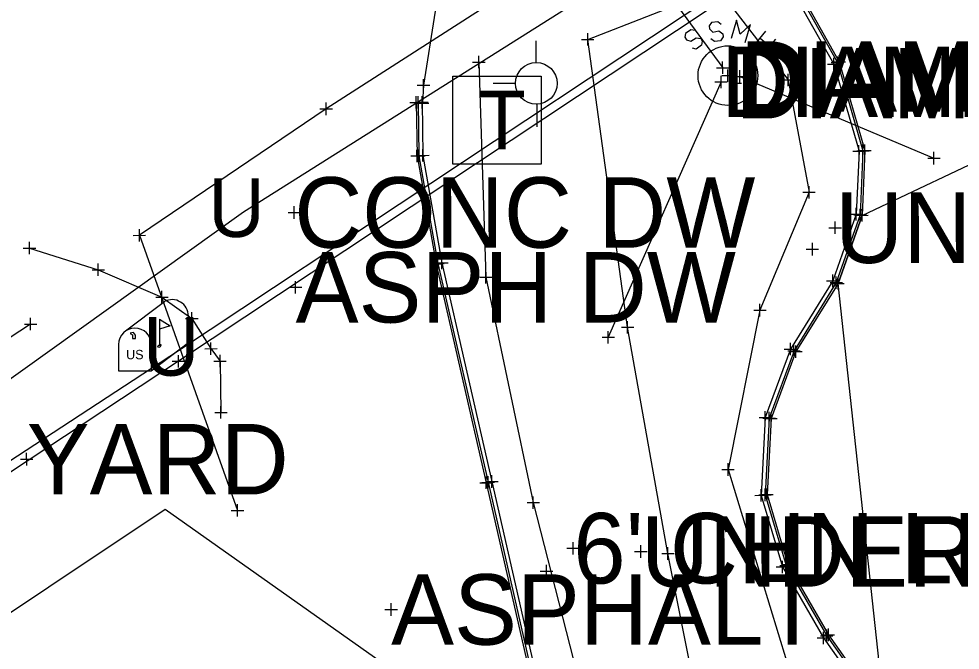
# Model space of a CAD drawing. Extents: x -1 to 1157254, y -1 to 2021979.
# Drawn here: x 1150680.9 to 1150776.9, y 2019832.5 to 2019897 of the extents above; entities that cross this region are included whole.
import ezdxf

# ---------------------------------------------------------------- set-up
doc = ezdxf.new("R2010")
doc.units = 0
for name, color, linetype in [('S_BUILDING_ANNOT', 7, 'Continuous'), ('S_CAL_CORNER_ANNOT', 7, 'Continuous'), ('S_CATCH_BASIN', 7, 'Continuous'), ('S_CATCH_BASIN_ANNOT', 7, 'Continuous'), ('S_CONTOUR_MAJOR', 7, 'Continuous'), ('S_CONTOUR_MINOR', 7, 'Continuous'), ('S_CROSS_DRAIN', 7, 'Continuous'), ('S_CTL_TABLE', 7, 'Continuous'), ('S_DROP_INLET', 7, 'Continuous'), ('S_EDGE_BITUMINOUS_ANNOT', 7, 'Continuous'), ('S_EDGE_PAVEMENT', 7, 'Continuous'), ('S_EDGE_PAVEMENT_ANNOT', 7, 'Continuous'), ('S_ENV_CONSTRAINT', 7, 'Continuous'), ('S_FENCE', 7, 'Continuous'), ('S_GAS_PUMP_ISLAND_ANNOT', 7, 'Continuous'), ('S_GATE', 7, 'Continuous')]:
    doc.layers.add(name, color=color, linetype=linetype)

msp = doc.modelspace()

# ---------------------------------------------------------------- linework, layer by layer
at = {"layer": 'S_BUILDING_ANNOT'}
for p, q in [((1150764.407, 2019891.922), (1150764.404, 2019893.194)), ((1150764.593, 2019891.999), (1150764.59, 2019893.271)), ((1150752.694, 2019891.403), (1150752.691, 2019892.675)), ((1150752.694, 2019891.403), (1150752.691, 2019892.675)), ((1150763.398, 2019892.401), (1150764.671, 2019892.403)), ((1150763.769, 2019892.557), (1150765.042, 2019892.559)), ((1150763.955, 2019892.634), (1150765.228, 2019892.636)), ((1150764.036, 2019891.766), (1150764.033, 2019893.038)), ((1150764.035, 2019892.402), (1150764.035, 2019892.402)), ((1150764.406, 2019892.558), (1150764.406, 2019892.558)), ((1150764.592, 2019892.635), (1150764.592, 2019892.635)), ((1150752.056, 2019892.038), (1150753.328, 2019892.04)), ((1150752.056, 2019892.038), (1150753.328, 2019892.04)), ((1150752.525, 2019889.952), (1150752.522, 2019891.224)), ((1150752.525, 2019889.952), (1150752.522, 2019891.224)), ((1150752.59, 2019891.227), (1150753.862, 2019891.23)), ((1150752.692, 2019892.039), (1150752.692, 2019892.039)), ((1150752.692, 2019892.039), (1150752.692, 2019892.039)), ((1150753.228, 2019890.593), (1150753.225, 2019891.865)), ((1150753.226, 2019891.229), (1150753.226, 2019891.229)), ((1150754.46, 2019890.5), (1150754.457, 2019891.772)), ((1150754.46, 2019890.5), (1150754.457, 2019891.772)), ((1150721.523, 2019890.247), (1150722.795, 2019890.25)), ((1150722.16, 2019889.613), (1150722.158, 2019890.885)), ((1150722.159, 2019890.249), (1150722.159, 2019890.249)), ((1150751.887, 2019890.586), (1150753.159, 2019890.589)), ((1150751.887, 2019890.586), (1150753.159, 2019890.589)), ((1150752.523, 2019890.588), (1150752.523, 2019890.588)), ((1150752.523, 2019890.588), (1150752.523, 2019890.588)), ((1150753.35, 2019890.455), (1150754.622, 2019890.458)), ((1150753.35, 2019890.455), (1150754.622, 2019890.458)), ((1150753.822, 2019891.134), (1150755.094, 2019891.137)), ((1150753.822, 2019891.134), (1150755.094, 2019891.137)), ((1150753.988, 2019889.821), (1150753.985, 2019891.093)), ((1150753.988, 2019889.821), (1150753.985, 2019891.093)), ((1150753.986, 2019890.457), (1150753.986, 2019890.457)), ((1150753.986, 2019890.457), (1150753.986, 2019890.457)), ((1150754.458, 2019891.136), (1150754.458, 2019891.136)), ((1150754.458, 2019891.136), (1150754.458, 2019891.136)), ((1150712.227, 2019887.208), (1150712.224, 2019888.481)), ((1150720.773, 2019888.498), (1150722.045, 2019888.501)), ((1150720.973, 2019888.501), (1150722.245, 2019888.504)), ((1150721.373, 2019888.507), (1150722.645, 2019888.51)), ((1150721.41, 2019887.863), (1150721.408, 2019889.136)), ((1150721.409, 2019888.5), (1150721.409, 2019888.5)), ((1150721.423, 2019888.431), (1150722.695, 2019888.434)), ((1150721.61, 2019887.866), (1150721.608, 2019889.139)), ((1150721.609, 2019888.503), (1150721.609, 2019888.503)), ((1150722.01, 2019887.872), (1150722.008, 2019889.145)), ((1150722.009, 2019888.509), (1150722.009, 2019888.509)), ((1150722.06, 2019887.796), (1150722.058, 2019889.069)), ((1150722.059, 2019888.433), (1150722.059, 2019888.433)), ((1150711.589, 2019887.843), (1150712.862, 2019887.846)), ((1150712.226, 2019887.845), (1150712.226, 2019887.845)), ((1150721.494, 2019882.394), (1150721.492, 2019883.667)), ((1150721.694, 2019882.413), (1150721.692, 2019883.686)), ((1150722.093, 2019882.451), (1150722.091, 2019883.724)), ((1150765.97, 2019883.498), (1150767.243, 2019883.501)), ((1150766.372, 2019883.547), (1150767.645, 2019883.55)), ((1150766.573, 2019883.571), (1150767.846, 2019883.574)), ((1150766.608, 2019882.863), (1150766.605, 2019884.136)), ((1150766.607, 2019883.499), (1150766.607, 2019883.499)), ((1150767.01, 2019882.912), (1150767.007, 2019884.185)), ((1150767.009, 2019883.548), (1150767.009, 2019883.548)), ((1150767.211, 2019882.936), (1150767.208, 2019884.209)), ((1150767.21, 2019883.572), (1150767.21, 2019883.572)), ((1150720.857, 2019883.029), (1150722.129, 2019883.032)), ((1150721.057, 2019883.048), (1150722.329, 2019883.051)), ((1150721.456, 2019883.086), (1150722.728, 2019883.089)), ((1150721.493, 2019883.03), (1150721.493, 2019883.03)), ((1150721.693, 2019883.049), (1150721.693, 2019883.049)), ((1150722.092, 2019883.087), (1150722.092, 2019883.087)), ((1150773.624, 2019882.796), (1150774.896, 2019882.799)), ((1150774.261, 2019882.161), (1150774.259, 2019883.434)), ((1150774.26, 2019882.797), (1150774.26, 2019882.797)), ((1150708.965, 2019876.615), (1150708.962, 2019877.888)), ((1150766.329, 2019876.438), (1150766.326, 2019877.711)), ((1150708.327, 2019877.25), (1150709.6, 2019877.253)), ((1150708.963, 2019877.251), (1150708.963, 2019877.251)), ((1150765.691, 2019877.073), (1150766.964, 2019877.076)), ((1150766.088, 2019876.996), (1150767.361, 2019876.999)), ((1150766.286, 2019876.958), (1150767.559, 2019876.961)), ((1150766.328, 2019877.074), (1150766.328, 2019877.074)), ((1150766.726, 2019876.361), (1150766.723, 2019877.634)), ((1150766.725, 2019876.997), (1150766.725, 2019876.997)), ((1150766.924, 2019876.323), (1150766.921, 2019877.596)), ((1150766.923, 2019876.959), (1150766.923, 2019876.959)), ((1150764.173, 2019875.057), (1150764.17, 2019876.329)), ((1150692.521, 2019874.915), (1150693.793, 2019874.918)), ((1150693.158, 2019874.28), (1150693.156, 2019875.552)), ((1150693.157, 2019874.916), (1150693.157, 2019874.916)), ((1150763.535, 2019875.692), (1150764.808, 2019875.695)), ((1150764.172, 2019875.693), (1150764.172, 2019875.693)), ((1150681.947, 2019872.982), (1150681.944, 2019874.254)), ((1150761.853, 2019872.869), (1150761.85, 2019874.141)), ((1150681.309, 2019873.617), (1150682.582, 2019873.62)), ((1150681.945, 2019873.618), (1150681.945, 2019873.618)), ((1150761.215, 2019873.504), (1150762.488, 2019873.506)), ((1150761.852, 2019873.505), (1150761.852, 2019873.505)), ((1150688.96, 2019870.77), (1150688.957, 2019872.042)), ((1150722.797, 2019871.986), (1150724.069, 2019871.988)), ((1150722.993, 2019872.026), (1150724.265, 2019872.028)), ((1150723.385, 2019872.105), (1150724.657, 2019872.107)), ((1150723.434, 2019871.351), (1150723.432, 2019872.623)), ((1150723.433, 2019871.987), (1150723.433, 2019871.987)), ((1150723.63, 2019871.391), (1150723.628, 2019872.663)), ((1150723.629, 2019872.027), (1150723.629, 2019872.027)), ((1150724.022, 2019871.47), (1150724.02, 2019872.742)), ((1150724.021, 2019872.106), (1150724.021, 2019872.106)), ((1150688.323, 2019871.405), (1150689.595, 2019871.407)), ((1150688.959, 2019871.406), (1150688.959, 2019871.406)), ((1150709.108, 2019868.974), (1150709.105, 2019870.246)), ((1150763.291, 2019870.263), (1150764.564, 2019870.265)), ((1150763.654, 2019870.089), (1150764.927, 2019870.091)), ((1150763.929, 2019869.628), (1150763.926, 2019870.9)), ((1150763.928, 2019870.264), (1150763.928, 2019870.264)), ((1150764.292, 2019869.454), (1150764.289, 2019870.726)), ((1150764.291, 2019870.09), (1150764.291, 2019870.09)), ((1150764.473, 2019869.367), (1150764.47, 2019870.639)), ((1150695.465, 2019867.962), (1150695.463, 2019869.234)), ((1150708.47, 2019869.609), (1150709.743, 2019869.611)), ((1150709.106, 2019869.61), (1150709.106, 2019869.61)), ((1150763.835, 2019870.002), (1150765.108, 2019870.004)), ((1150764.472, 2019870.003), (1150764.472, 2019870.003)), ((1150694.828, 2019868.597), (1150696.1, 2019868.599)), ((1150695.464, 2019868.598), (1150695.464, 2019868.598)), ((1150682.055, 2019865.214), (1150682.052, 2019866.486)), ((1150697.878, 2019866.423), (1150699.15, 2019866.425)), ((1150698.515, 2019865.788), (1150698.513, 2019867.06)), ((1150698.514, 2019866.424), (1150698.514, 2019866.424)), ((1150681.417, 2019865.849), (1150682.69, 2019865.851)), ((1150682.053, 2019865.85), (1150682.053, 2019865.85)), ((1150740.383, 2019864.499), (1150741.656, 2019864.502)), ((1150741.021, 2019863.865), (1150741.018, 2019865.137)), ((1150741.02, 2019864.501), (1150741.02, 2019864.501)), ((1150699.828, 2019863.338), (1150701.1, 2019863.341)), ((1150700.466, 2019862.704), (1150700.463, 2019863.976)), ((1150700.464, 2019863.34), (1150700.464, 2019863.34)), ((1150758.976, 2019863.298), (1150760.249, 2019863.301)), ((1150759.614, 2019862.664), (1150759.611, 2019863.936)), ((1150759.612, 2019863.3), (1150759.612, 2019863.3)), ((1150759.975, 2019862.488), (1150759.972, 2019863.76)), ((1150760.156, 2019862.4), (1150760.153, 2019863.672)), ((1150697.154, 2019861.413), (1150697.152, 2019862.686)), ((1150701.396, 2019861.439), (1150701.393, 2019862.712)), ((1150759.337, 2019863.122), (1150760.61, 2019863.125)), ((1150759.518, 2019863.034), (1150760.791, 2019863.037)), ((1150759.973, 2019863.124), (1150759.973, 2019863.124)), ((1150760.154, 2019863.036), (1150760.154, 2019863.036)), ((1150696.517, 2019862.048), (1150697.789, 2019862.051)), ((1150697.153, 2019862.05), (1150697.153, 2019862.05)), ((1150700.758, 2019862.074), (1150702.03, 2019862.077)), ((1150701.394, 2019862.076), (1150701.394, 2019862.076)), ((1150700.846, 2019856.827), (1150702.118, 2019856.83)), ((1150701.484, 2019856.192), (1150701.481, 2019857.465)), ((1150701.482, 2019856.828), (1150701.482, 2019856.828)), ((1150757.041, 2019855.682), (1150757.038, 2019856.955)), ((1150757.437, 2019855.6), (1150757.434, 2019856.873)), ((1150757.635, 2019855.559), (1150757.632, 2019856.832)), ((1150756.403, 2019856.317), (1150757.676, 2019856.32)), ((1150756.799, 2019856.235), (1150758.072, 2019856.238)), ((1150756.997, 2019856.194), (1150758.27, 2019856.197)), ((1150757.039, 2019856.318), (1150757.039, 2019856.318)), ((1150757.435, 2019856.236), (1150757.435, 2019856.236)), ((1150757.633, 2019856.195), (1150757.633, 2019856.195)), ((1150681.017, 2019852.046), (1150682.29, 2019852.049)), ((1150681.655, 2019851.411), (1150681.652, 2019852.684)), ((1150681.654, 2019852.047), (1150681.654, 2019852.047)), ((1150728.558, 2019849.004), (1150728.555, 2019850.276)), ((1150728.753, 2019849.048), (1150728.75, 2019850.32)), ((1150729.143, 2019849.137), (1150729.14, 2019850.41)), ((1150727.92, 2019849.639), (1150729.193, 2019849.642)), ((1150728.115, 2019849.683), (1150729.388, 2019849.686)), ((1150728.505, 2019849.772), (1150729.778, 2019849.775)), ((1150728.556, 2019849.64), (1150728.556, 2019849.64)), ((1150728.751, 2019849.684), (1150728.751, 2019849.684)), ((1150729.141, 2019849.773), (1150729.141, 2019849.773)), ((1150756.615, 2019847.718), (1150756.612, 2019848.99)), ((1150757.018, 2019847.766), (1150757.015, 2019849.038)), ((1150757.219, 2019847.79), (1150757.216, 2019849.062)), ((1150755.977, 2019848.353), (1150757.25, 2019848.356)), ((1150756.38, 2019848.401), (1150757.653, 2019848.404)), ((1150756.581, 2019848.425), (1150757.854, 2019848.428)), ((1150756.613, 2019848.354), (1150756.613, 2019848.354)), ((1150757.016, 2019848.402), (1150757.016, 2019848.402)), ((1150757.217, 2019848.426), (1150757.217, 2019848.426)), ((1150703.174, 2019846.183), (1150703.171, 2019847.455)), ((1150702.536, 2019846.818), (1150703.809, 2019846.82)), ((1150703.172, 2019846.819), (1150703.172, 2019846.819)), ((1150737.439, 2019842.315), (1150737.436, 2019843.587)), ((1150744.342, 2019841.987), (1150744.34, 2019843.259)), ((1150736.801, 2019842.95), (1150738.074, 2019842.952)), ((1150737.438, 2019842.951), (1150737.438, 2019842.951)), ((1150743.705, 2019842.622), (1150744.977, 2019842.624)), ((1150744.341, 2019842.623), (1150744.341, 2019842.623)), ((1150734.715, 2019839.983), (1150734.712, 2019841.255)), ((1150758.537, 2019841.198), (1150759.81, 2019841.2)), ((1150758.722, 2019841.277), (1150759.995, 2019841.279)), ((1150758.805, 2019840.404), (1150758.802, 2019841.676)), ((1150759.175, 2019840.563), (1150759.172, 2019841.835)), ((1150759.173, 2019841.199), (1150759.173, 2019841.199)), ((1150759.36, 2019840.642), (1150759.357, 2019841.914)), ((1150759.358, 2019841.278), (1150759.358, 2019841.278)), ((1150734.077, 2019840.618), (1150735.35, 2019840.62)), ((1150734.713, 2019840.619), (1150734.713, 2019840.619)), ((1150758.167, 2019841.039), (1150759.44, 2019841.041)), ((1150758.803, 2019841.04), (1150758.803, 2019841.04)), ((1150718.214, 2019836.693), (1150719.486, 2019836.696)), ((1150718.851, 2019836.059), (1150718.849, 2019837.331)), ((1150718.85, 2019836.695), (1150718.85, 2019836.695)), ((1150763.316, 2019833.366), (1150763.313, 2019834.639)), ((1150763.485, 2019833.474), (1150763.482, 2019834.747)), ((1150762.34, 2019833.786), (1150763.613, 2019833.789)), ((1150762.678, 2019834.001), (1150763.951, 2019834.004)), ((1150762.847, 2019834.109), (1150764.12, 2019834.112)), ((1150762.978, 2019833.151), (1150762.975, 2019834.424)), ((1150762.977, 2019833.788), (1150762.977, 2019833.788)), ((1150763.315, 2019834.003), (1150763.315, 2019834.003)), ((1150763.484, 2019834.111), (1150763.484, 2019834.111))]:
    msp.add_line(p, q, dxfattribs=at)
at = {"layer": 'S_CAL_CORNER_ANNOT'}
for points in [[(1150880.608, 2019997.073), (1150845.227, 2019974.01), (1150778.479, 2019930.401), (1150712.226, 2019887.845), (1150693.157, 2019874.916), (1150703.172, 2019846.819)], [(1150682.053, 2019865.85), (1150601.539, 2019813.466), (1150510.576, 2019743.97), (1150405.278, 2019665.924), (1150310.689, 2019593.564), (1150188.917, 2019499.645), (1150039.447, 2019388.152), (1149962.145, 2019331.172), (1149944.629, 2019319.081), (1149774.148, 2019191.523), (1149712.731, 2019145.599), (1149665.813, 2019108.741), (1149605.459, 2019057.655), (1149527.462, 2018983.577), (1149450.124, 2018902.925), (1149278.324, 2018738.815), (1149257.196, 2018716.377), (1149237.235, 2018691.248), (1149165.086, 2018617.774), (1149125.259, 2018579.565), (1149069.496, 2018523.84), (1149012.034, 2018473.774), (1148938.876, 2018408.555)]]:
    msp.add_lwpolyline(points, dxfattribs=at)
at = {"layer": 'S_CATCH_BASIN'}
for p, q in [((1150733.668, 2019892.549), (1150733.668, 2019894.796)), ((1150731.576, 2019890.419), (1150729.252, 2019890.419)), ((1150733.745, 2019886.003), (1150733.745, 2019888.327))]:
    msp.add_line(p, q, dxfattribs=at)
msp.add_circle((1150733.67, 2019890.44), 2.127, dxfattribs=at)
at = {"layer": 'S_CATCH_BASIN_ANNOT'}
msp.add_lwpolyline([(1150725.153, 2019882.193), (1150725.153, 2019891.19), (1150734.15, 2019891.19), (1150734.15, 2019882.193)], close=True, dxfattribs=at)
at = {"layer": 'S_CONTOUR_MINOR'}
for p, q in [((1150748.901, 2019895.53), (1150748.824, 2019895.143)), ((1150748.824, 2019895.143), (1150749.017, 2019894.872)), ((1150749.443, 2019895.918), (1150748.901, 2019895.53)), ((1150749.869, 2019895.84), (1150749.443, 2019895.918)), ((1150749.443, 2019894.756), (1150749.986, 2019895.104)), ((1150749.986, 2019895.104), (1150750.45, 2019895.027)), ((1150750.45, 2019895.027), (1150750.605, 2019894.756)), ((1150755.873, 2019894.291), (1150757.113, 2019895.763)), ((1150756.532, 2019895.065), (1150757.5, 2019894.252)), ((1150749.017, 2019894.872), (1150749.443, 2019894.756)), ((1150750.528, 2019894.329), (1150749.986, 2019893.942)), ((1150750.605, 2019894.756), (1150750.528, 2019894.329)), ((1150758.081, 2019894.949), (1150756.842, 2019893.477)), ((1150749.986, 2019893.942), (1150749.598, 2019894.02))]:
    msp.add_line(p, q, dxfattribs=at)
for points in [[(1150692.776, 2019973.706), (1150752.692, 2019892.039)], [(1150752.542, 2019896.46), (1150752.194, 2019896.731), (1150751.535, 2019896.654), (1150751.303, 2019896.305), (1150751.341, 2019895.995), (1150751.69, 2019895.685), (1150752.31, 2019895.801), (1150752.697, 2019895.492), (1150752.736, 2019895.182), (1150752.465, 2019894.794), (1150751.845, 2019894.717), (1150751.496, 2019894.988)], [(1150754.982, 2019894.601), (1150755.525, 2019896.46), (1150754.479, 2019895.453), (1150754.092, 2019896.886), (1150753.549, 2019895.027)], [(1150752.523, 2019890.588), (1150741.02, 2019864.501)], [(1150754.458, 2019891.136), (1150774.26, 2019882.797)]]:
    msp.add_lwpolyline(points, dxfattribs=at)
msp.add_circle((1150753.226, 2019891.229), 3.047, dxfattribs=at)
at = {"layer": 'S_CROSS_DRAIN'}
for p, q in [((1150691.592, 2019865.049), (1150695.725, 2019868.156)), ((1150695.206, 2019866.337), (1150695.206, 2019863.623)), ((1150698.155, 2019866.683), (1150698.155, 2019863.969)), ((1150691.038, 2019863.775), (1150691.038, 2019861.061)), ((1150694.361, 2019861.061), (1150698.155, 2019863.969)), ((1150694.361, 2019863.775), (1150694.361, 2019861.061)), ((1150691.038, 2019861.061), (1150694.361, 2019861.061))]:
    msp.add_line(p, q, dxfattribs=at)
for points in [[(1150695.206, 2019866.337), (1150696.314, 2019865.672), (1150695.206, 2019865.326)], [(1150692.222, 2019864.89), (1150692.444, 2019864.751), (1150692.444, 2019864.364), (1150692.748, 2019864.364), (1150692.748, 2019864.724), (1150692.554, 2019864.973), (1150692.222, 2019864.917)]]:
    msp.add_lwpolyline(points, dxfattribs=at)
for centre, end in [((1150696.494, 2019866.683), 117.57184), ((1150692.7, 2019863.775), 180)]:
    msp.add_arc(centre, 1.662, 0, end, dxfattribs=at)
msp.add_ellipse((1150695.206, 2019863.623), major_axis=(0.145, 0.132), ratio=0.564646, dxfattribs=at)
at = {"layer": 'S_CTL_TABLE'}
for p, q in [((1150738.921, 2019894.296), (1150738.918, 2019895.568)), ((1150738.283, 2019894.931), (1150739.556, 2019894.933)), ((1150738.92, 2019894.932), (1150738.92, 2019894.932)), ((1150727.803, 2019891.976), (1150727.8, 2019893.248)), ((1150727.165, 2019892.611), (1150728.437, 2019892.613)), ((1150727.801, 2019892.612), (1150727.801, 2019892.612)), ((1150759.366, 2019890.159), (1150759.363, 2019891.431)), ((1150758.728, 2019890.793), (1150760.001, 2019890.796)), ((1150759.364, 2019890.795), (1150759.364, 2019890.795)), ((1150761.514, 2019878.68), (1150761.511, 2019879.953)), ((1150760.876, 2019879.315), (1150762.149, 2019879.318)), ((1150761.512, 2019879.316), (1150761.512, 2019879.316)), ((1150728.524, 2019870.004), (1150728.521, 2019871.276)), ((1150727.886, 2019870.639), (1150729.159, 2019870.641)), ((1150728.522, 2019870.64), (1150728.522, 2019870.64)), ((1150755.864, 2019867.276), (1150757.137, 2019867.278)), ((1150756.502, 2019866.641), (1150756.499, 2019867.913)), ((1150756.5, 2019867.277), (1150756.5, 2019867.277)), ((1150742.351, 2019865.521), (1150743.623, 2019865.524)), ((1150742.988, 2019864.887), (1150742.985, 2019866.159)), ((1150742.987, 2019865.523), (1150742.987, 2019865.523)), ((1150752.609, 2019850.999), (1150753.881, 2019851.002)), ((1150753.247, 2019850.364), (1150753.244, 2019851.637)), ((1150753.245, 2019851), (1150753.245, 2019851)), ((1150733.365, 2019846.976), (1150733.362, 2019848.248)), ((1150732.727, 2019847.611), (1150734, 2019847.614)), ((1150733.363, 2019847.612), (1150733.363, 2019847.612)), ((1150746.473, 2019842.415), (1150747.745, 2019842.417)), ((1150747.11, 2019841.78), (1150747.108, 2019843.052)), ((1150747.109, 2019842.416), (1150747.109, 2019842.416))]:
    msp.add_line(p, q, dxfattribs=at)
at = {"layer": 'S_DROP_INLET'}
for points in [[(1150852.18, 2019973.051), (1150778.535, 2019928.447), (1150770.156, 2019919.184), (1150703.801, 2019877.293), (1150608.628, 2019809.117), (1150513.433, 2019739.889), (1150405.923, 2019663.647), (1150352.205, 2019622.717), (1150343.813, 2019614.735), (1150336.716, 2019606.983), (1150314.894, 2019591.844), (1150193.248, 2019498.282), (1150112.687, 2019435.49), (1150059.592, 2019406.164), (1150037.875, 2019389.795), (1149962.987, 2019329.909), (1149914.051, 2019297.396), (1149863.257, 2019256.982)], [(1150853.563, 2019969.995), (1150781.705, 2019924.443), (1150774.41, 2019914.43), (1150697.133, 2019863.122), (1150609.243, 2019805.568), (1150516.577, 2019735.983), (1150408.735, 2019655.565), (1150359.482, 2019622.09), (1150352.765, 2019615.317), (1150355.197, 2019603.603), (1150359.346, 2019593.869)]]:
    msp.add_lwpolyline(points, dxfattribs=at)
at = {"layer": 'S_EDGE_BITUMINOUS_ANNOT'}
msp.add_lwpolyline([(1150727.801, 2019892.612), (1150728.522, 2019870.64), (1150733.363, 2019847.612), (1150741.176, 2019817.005), (1150751.169, 2019821.991), (1150747.109, 2019842.416), (1150742.987, 2019865.523), (1150738.92, 2019894.932), (1150752.196, 2019900.137), (1150759.364, 2019890.795), (1150761.512, 2019879.316), (1150756.5, 2019867.277), (1150753.245, 2019851), (1150759.208, 2019831.444)], dxfattribs=at)
at = {"layer": 'S_EDGE_PAVEMENT'}
for points in [[(1150753.192, 2019906.889), (1150755.737, 2019904.784), (1150759.82, 2019899.891), (1150764.035, 2019892.402), (1150766.607, 2019883.499), (1150766.328, 2019877.074), (1150763.928, 2019870.264), (1150759.612, 2019863.3), (1150757.039, 2019856.318), (1150756.613, 2019848.354), (1150758.803, 2019841.04), (1150762.977, 2019833.788), (1150774.66, 2019817.171)], [(1150753.447, 2019907.197), (1150756.021, 2019905.069), (1150760.152, 2019900.119), (1150764.406, 2019892.558), (1150767.009, 2019883.548), (1150766.725, 2019876.997), (1150764.291, 2019870.09), (1150759.973, 2019863.124), (1150757.435, 2019856.236), (1150757.016, 2019848.402), (1150759.173, 2019841.199), (1150763.315, 2019834.003), (1150774.987, 2019817.401)], [(1150721.609, 2019888.503), (1150721.693, 2019883.049), (1150723.629, 2019872.027), (1150728.751, 2019849.684), (1150733.581, 2019828.453), (1150741.893, 2019794.222)], [(1150722.009, 2019888.509), (1150722.092, 2019883.087), (1150724.021, 2019872.106), (1150729.141, 2019849.773), (1150733.969, 2019828.545), (1150742.282, 2019794.316)]]:
    msp.add_lwpolyline(points, dxfattribs=at)
at = {"layer": 'S_EDGE_PAVEMENT_ANNOT'}
msp.add_lwpolyline([(1150753.574, 2019907.351), (1150756.162, 2019905.211), (1150760.316, 2019900.234), (1150764.592, 2019892.635), (1150767.21, 2019883.572), (1150766.923, 2019876.959), (1150764.472, 2019870.003), (1150760.154, 2019863.036), (1150757.633, 2019856.195), (1150757.217, 2019848.426), (1150759.358, 2019841.278), (1150763.484, 2019834.111), (1150775.151, 2019817.516)], dxfattribs=at)
at = {"layer": 'S_ENV_CONSTRAINT'}
for points in [[(1150724.983, 2019902.1), (1150723.339, 2019897.82), (1150722.159, 2019890.249), (1150722.059, 2019888.433)], [(1150721.409, 2019888.5), (1150721.493, 2019883.03), (1150723.433, 2019871.987), (1150728.556, 2019849.64), (1150733.385, 2019828.407), (1150741.699, 2019794.174)], [(1150681.945, 2019873.618), (1150688.959, 2019871.406), (1150695.464, 2019868.598), (1150698.514, 2019866.424), (1150700.464, 2019863.34), (1150701.394, 2019862.076), (1150701.482, 2019856.828)]]:
    msp.add_lwpolyline(points, dxfattribs=at)
at = {"layer": 'S_FENCE'}
msp.add_lwpolyline([(1150775.157, 2019913.882), (1150697.153, 2019862.05), (1150611.536, 2019805.469), (1150516.858, 2019735.368), (1150402.982, 2019659.79), (1150352.978, 2019622.148), (1150350.249, 2019606.715), (1150331.339, 2019598.55), (1150196.241, 2019490.875), (1150043.622, 2019380.107), (1149966.768, 2019324.716), (1149934.21, 2019308.484), (1149916.332, 2019289.124), (1149866.677, 2019250.907)], dxfattribs=at)
at = {"layer": 'S_GAS_PUMP_ISLAND_ANNOT'}
msp.add_lwpolyline([(1150672.01, 2019831.088), (1150695.801, 2019846.938), (1150735.745, 2019818.69), (1150738.105, 2019808.972), (1150740.465, 2019799.255), (1150741.699, 2019794.174), (1150742.282, 2019794.316), (1150774.66, 2019817.171), (1150775.151, 2019817.516), (1150774.985, 2019817.752), (1150769.234, 2019825.931), (1150764.472, 2019870.003), (1150766.923, 2019876.959), (1150811.333, 2019897.978), (1150853.738, 2019880.826), (1150855.84, 2019878.747), (1150901.117, 2019859.564), (1150903.298, 2019856.052)], dxfattribs=at)

# ---------------------------------------------------------------- texts
at = {"layer": 'S_BUILDING_ANNOT'}
for p in [(1150752.523, 2019886.988), (1150753.986, 2019886.857), (1150754.458, 2019887.536)]:
    msp.add_text('DIAMETER?8"', height=7.2, dxfattribs=at).set_placement(p)
at = {"layer": 'S_CATCH_BASIN_ANNOT'}
msp.add_text('T', height=5.998, dxfattribs=at).set_placement((1150727.715, 2019883.693))
at = {"layer": 'S_CONTOUR_MAJOR'}
for p in [(1150700.173, 2019874.749), (1150693.505, 2019860.578)]:
    msp.add_text('U', height=5.998, dxfattribs=at).set_placement(p)
at = {"layer": 'S_CROSS_DRAIN'}
msp.add_text('US', height=0.9596, dxfattribs=at).set_placement((1150691.802, 2019862.254))
at = {"layer": 'S_GATE'}
for s, p in [('CONC DW', (1150708.963, 2019873.651)), ('UNDER CONSTRUCTION', (1150764.172, 2019872.093)), ('ASPH DW', (1150709.106, 2019866.01)), ('YARD', (1150681.654, 2019848.447)), ("6' CHN LNK GOOD", (1150737.438, 2019839.351)), ('UNDER CONSTRUCTION', (1150744.341, 2019839.023)), ('ASPHALT', (1150718.85, 2019833.095))]:
    msp.add_text(s, height=7.2, dxfattribs=at).set_placement(p)

doc.saveas('drawing.dxf')
